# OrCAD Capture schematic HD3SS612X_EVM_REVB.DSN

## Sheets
1 PAGE1_Block Power Diagram: size A4; title: HD3SS612x 2 to 1 switch; rev: 1.0; company: Texas Instrument
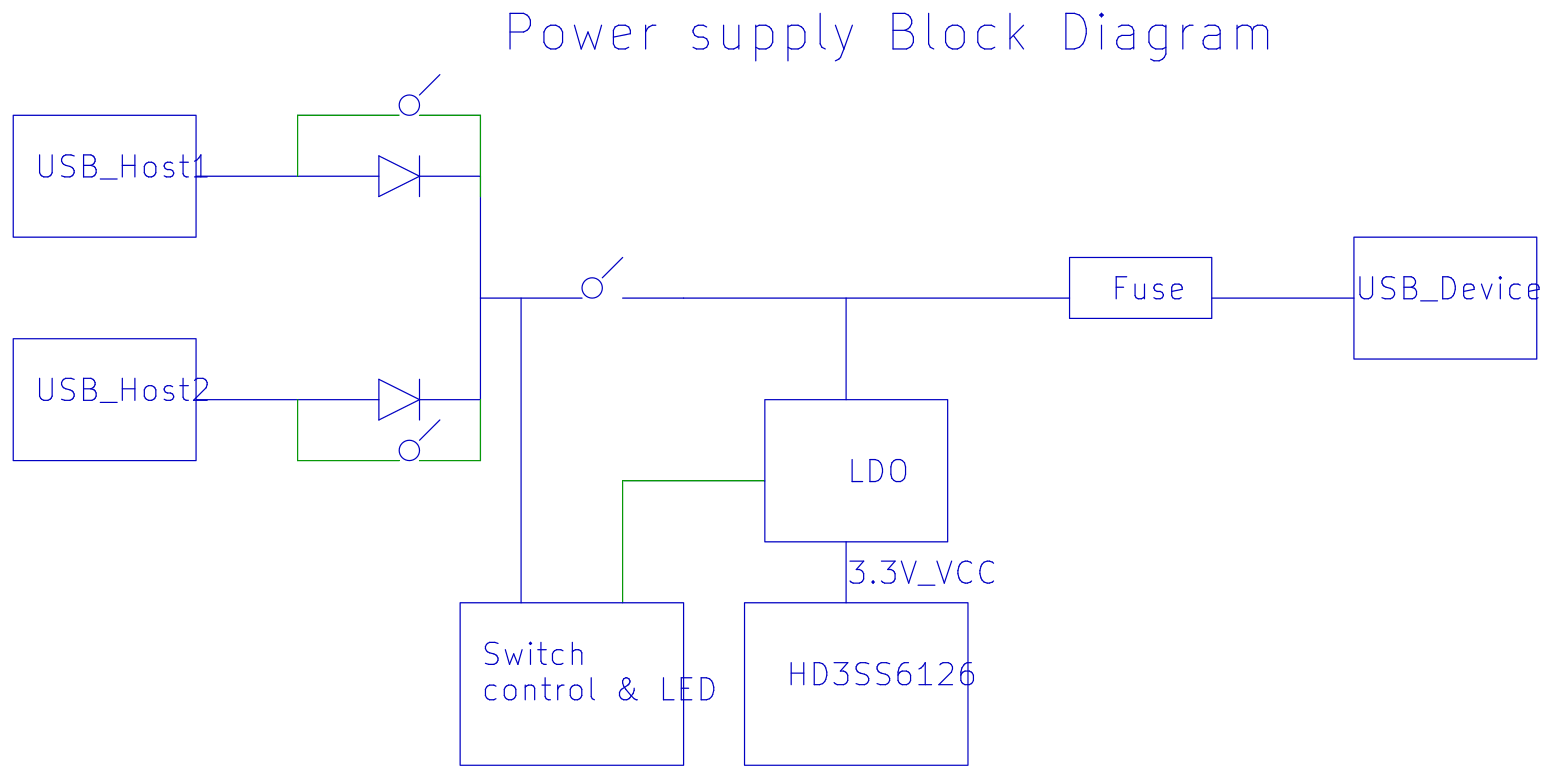
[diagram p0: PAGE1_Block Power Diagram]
2 PAGE4_USB_Micro-B Connectors: size A4
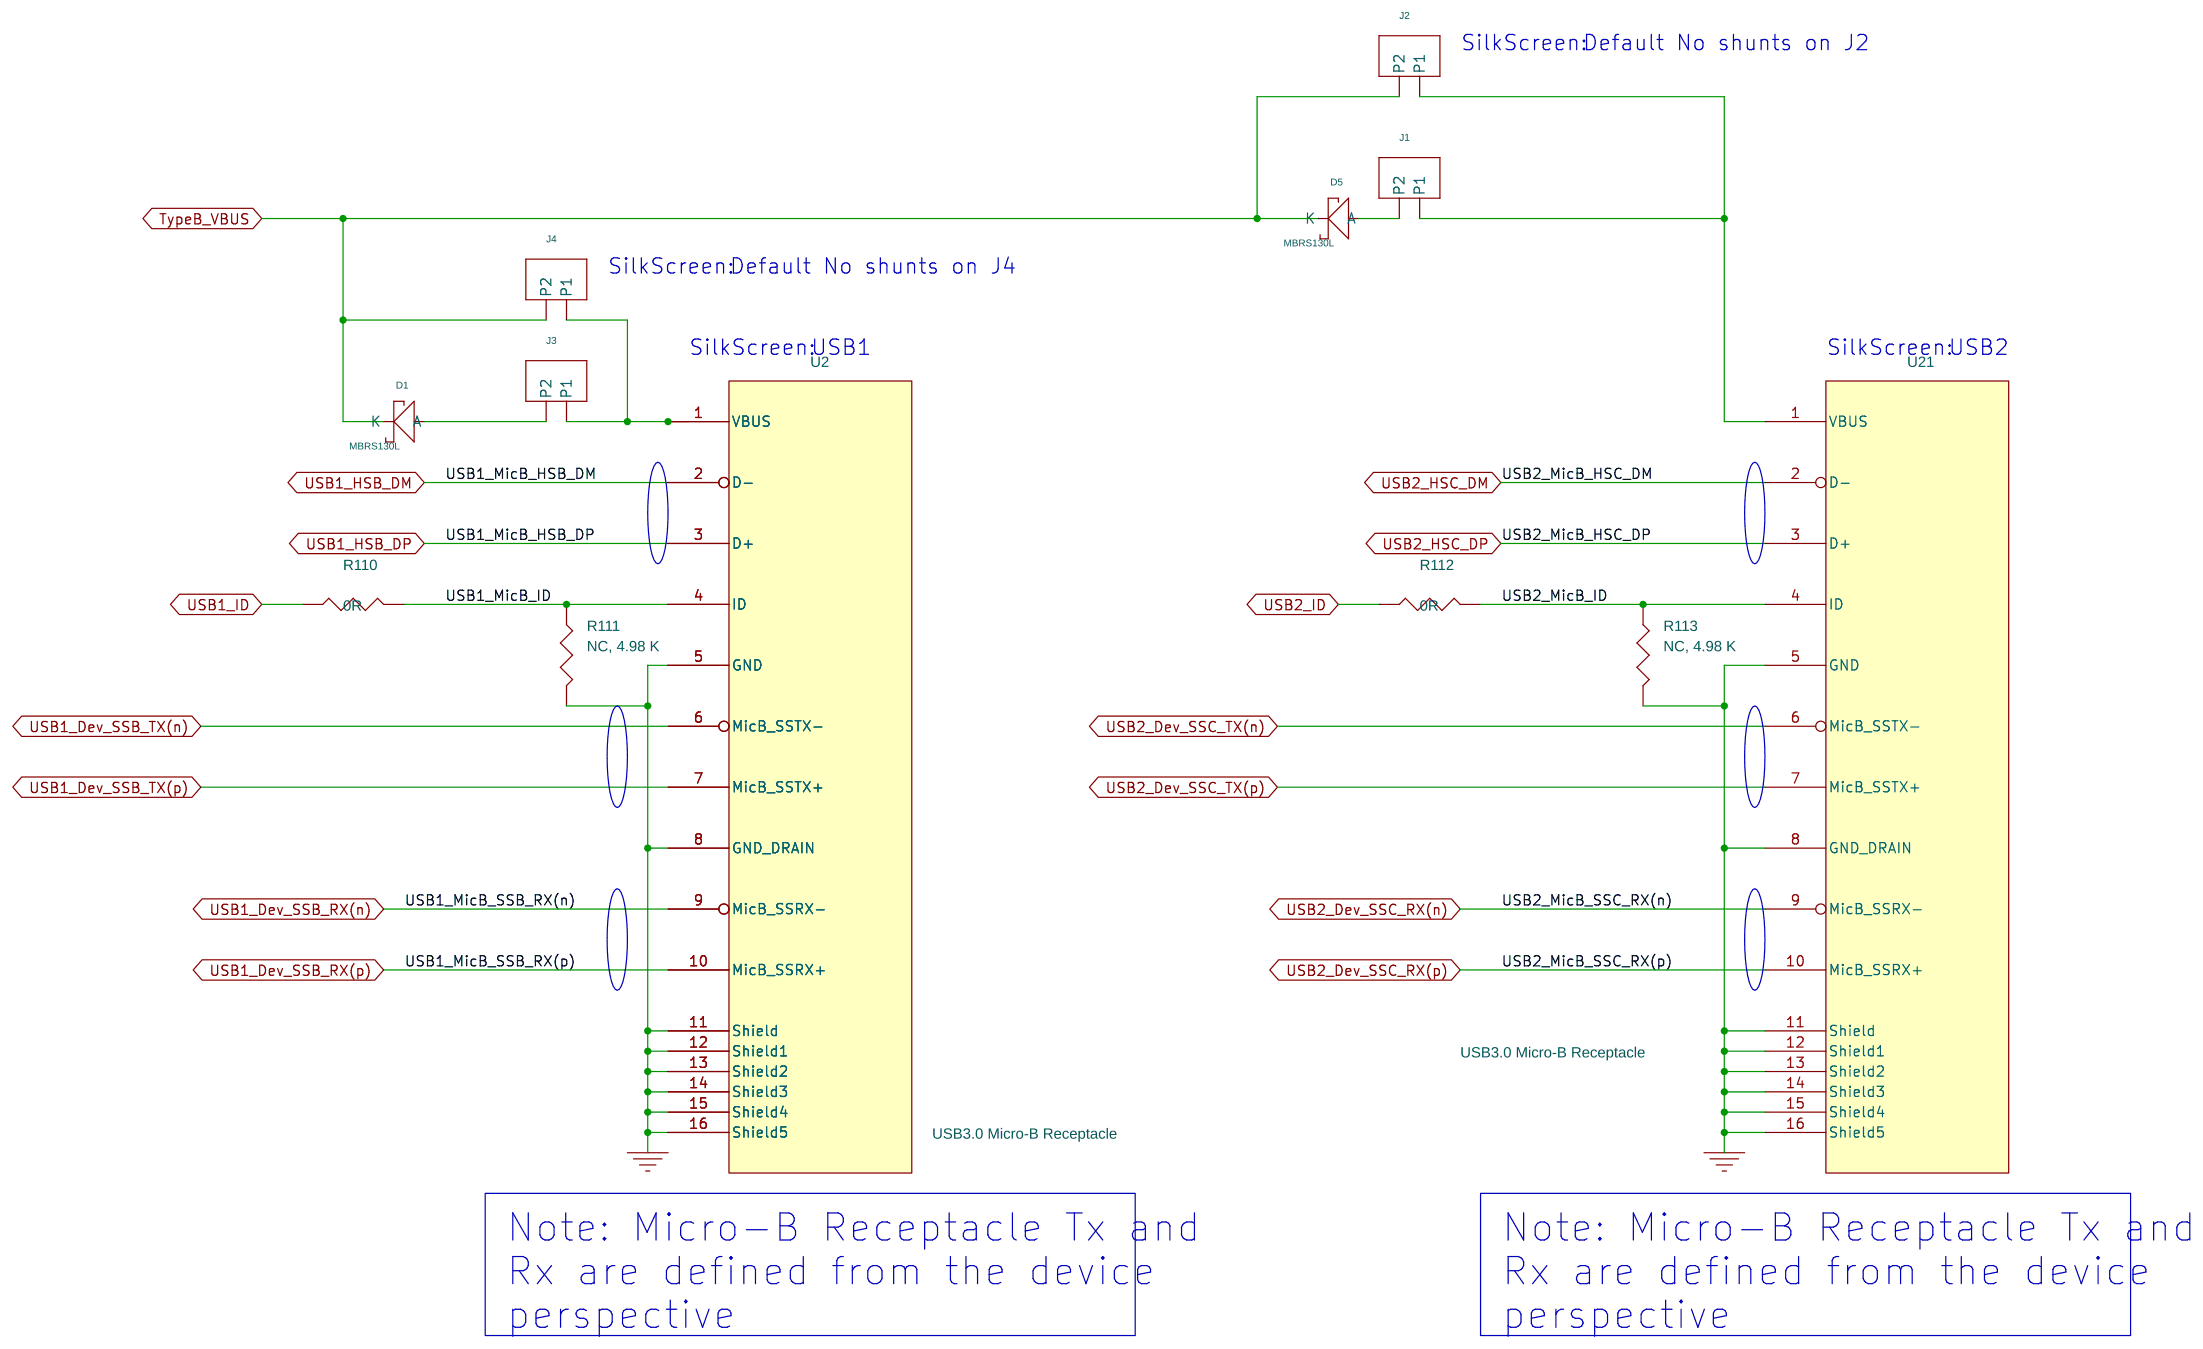
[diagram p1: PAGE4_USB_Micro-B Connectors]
3 PAGE3_Power and Switch control: size A4
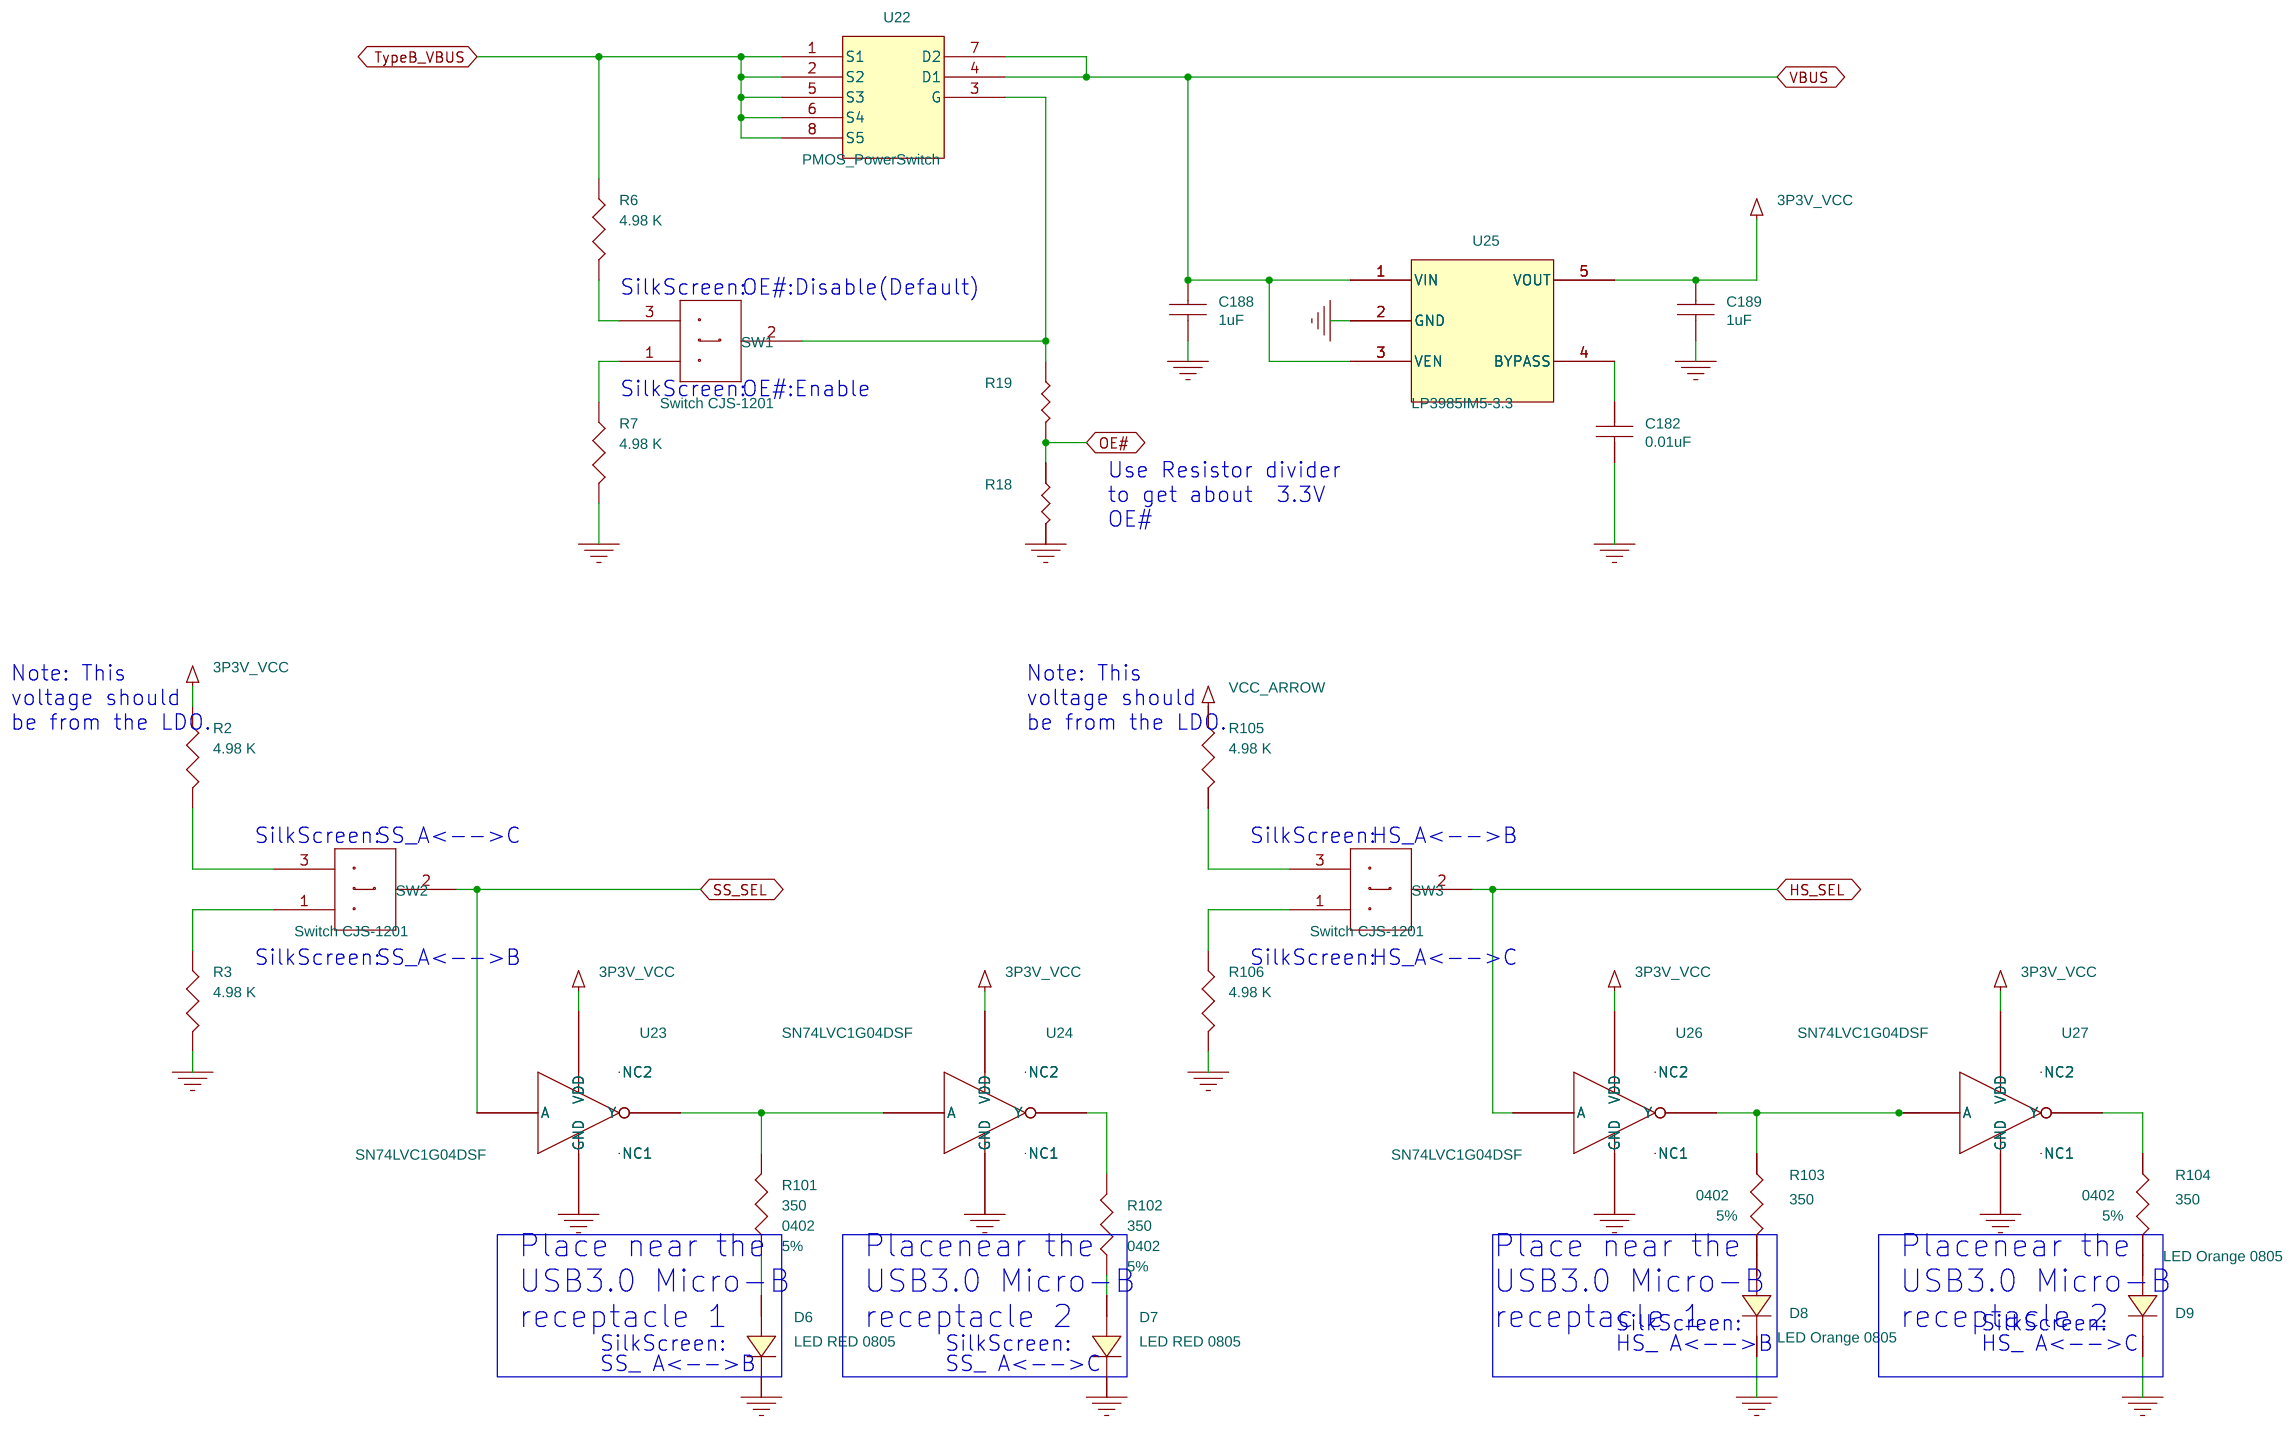
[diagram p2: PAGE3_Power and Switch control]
4 PAGE2_HD3SS6128: size A4
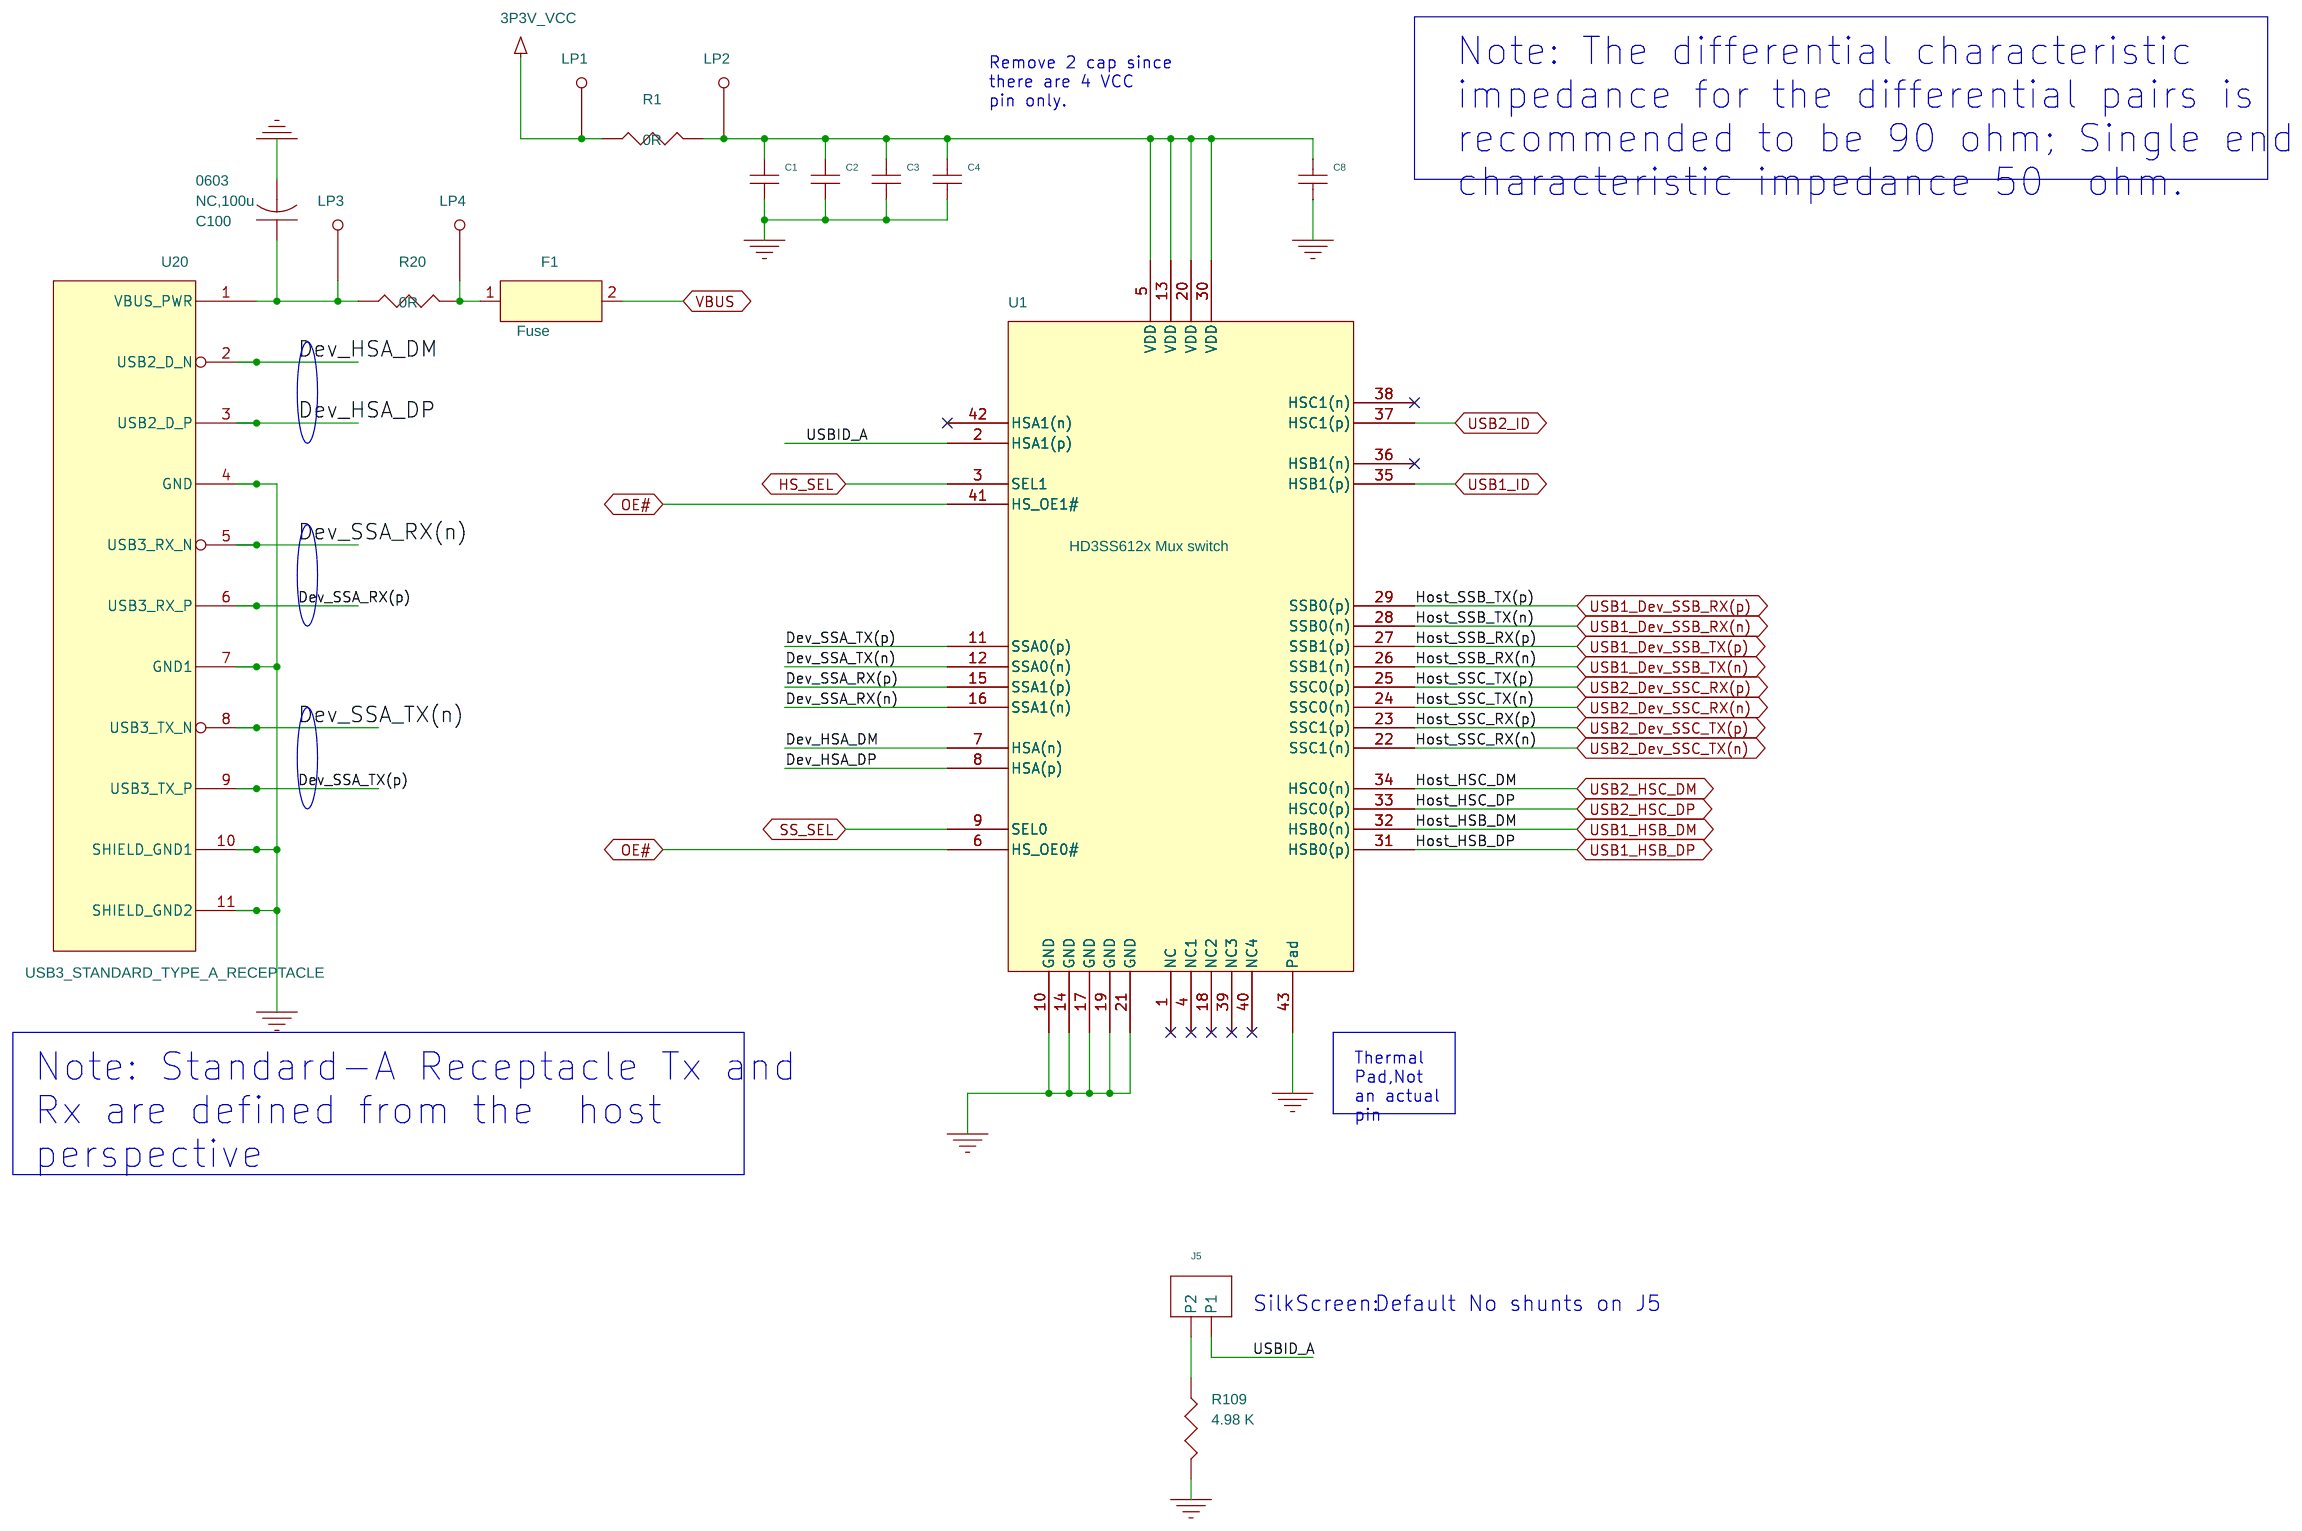
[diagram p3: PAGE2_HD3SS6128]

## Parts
sheet PAGE2_HD3SS6128
C1  0.1uF  [0402]
C2  0.1uF  [0402]
C3  0.1uF  [0402]
C4  0.1uF  [0402]
C8  NC, 10uF  [0805]
C100  NC,100u  [0603]
F1  Fuse  [1206]
J5  CON02  [BERG1X2]
LP1  LP  [TESTLOOP]
LP2  LP  [TESTLOOP]
LP3  LP  [TESTLOOP]
LP4  LP  [TESTLOOP]
R1  0R  [0402]
R20  0R  [0402]
R109  4.98 K  [0603]
U1  HD3SS612x Mux switch  [IRONWOOD_42pin_c9856]
U20  USB3_STANDARD_TYPE_A_RECEPTACLE  [usb3_typea]
sheet PAGE3_Power and Switch control
C182  0.01uF  [0402]
C188  1uF  [0603]
C189  1uF  [0603]
D6  LED RED 0805  [0805]
D7  LED RED 0805  [0805]
D8  LED Orange 0805  [0805]
D9  LED Orange 0805  [0805]
R2  4.98 K  [0603]
R3  4.98 K  [0603]
R6  4.98 K  [0603]
R7  4.98 K  [0603]
R18  100K  [0402]
R19  50K  [0402]
R101  350  [0402]
R102  350  [0402]
R103  350  [0402]
R104  350  [0402]
R105  4.98 K  [0603]
R106  4.98 K  [0603]
SW1  Switch CJS-1201  [CJS-1200B]
SW2  Switch CJS-1201  [CJS-1200B]
SW3  Switch CJS-1201  [CJS-1200B]
U22  PMOS_PowerSwitch  [csd25302q2]
U23  SN74LVC1G04DSF  [DSF]
U24  SN74LVC1G04DSF  [DSF]
U25  LP3985IM5-3.3  [dbv_r-pdso-g5]
U26  SN74LVC1G04DSF  [DSF]
U27  SN74LVC1G04DSF  [DSF]
sheet PAGE4_USB_Micro-B Connectors
D1  SCHOTTKY  [DO-214AA]
D5  SCHOTTKY  [DO-214AA]
J1  CON02  [BERG1X2]
J2  CON02  [BERG1X2]
J3  CON02  [BERG1X2]
J4  CON02  [BERG1X2]
R110  0R  [0402]
R111  NC, 4.98 K  [0603]
R112  0R  [0402]
R113  NC, 4.98 K  [0603]
U2  USB3.0 Micro-B Receptacle  [USB3_micro_b_receptacle]
U21  USB3.0 Micro-B Receptacle  [USB3_micro_b_receptacle]

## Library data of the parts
C1-C4 = CAP: 10V; $SEC: 1; ATIPartNo: 4170010400G; CDS_LIB: capacitor; DRAWING: @LIGHTNING_BOLT_NB_LIB.NOTE_BOOK(SCH_1):PAGE1; PHYS_PAGE: 1; ROT: 0; TOLERANCE: 10%; VER: 1; VOLTAGE: 10V; XY: (-8600,5400)
C8 = CAP: 6.3V; $SEC: 1; ATIPartNo: 4210010600G; CDS_LIB: capacitor; DRAWING: @LIGHTNING_BOLT_NB_LIB.NOTE_BOOK(SCH_1):PAGE1; PHYS_PAGE: 1; ROT: 0; TOLERANCE: 10%; VER: 1; VOLTAGE: 6.3V; XY: (-9500,3550)
C100 = PCap_CaseD: TYPE: Tantalum
F1 = Fuse_0
J1-J5 = CON02: ATIPartNo: 6010014900G; CDS_LIB: connector; DRAWING: @LIGHTNING_BOLT_NB_LIB.NOTE_BOOK(SCH_1):PAGE2; PHYS_PAGE: 2; ROT: 0; VER: 1; XY: (-8200,6300)
LP1-LP4 = TESTLOOP: Manuf: KOBIKONN; Manuf PN: 151-103-RC
R1 R20 R110 R112 = R: Resistor; Tolerance: 5%
R2 R3 R6 R7 R105 R106 R109 R111 R113 = r0603: Manufacturer: Any; Manufacturer Part Number: Any
U1 = HD3SS6126_Mux_switch_11
U20 = TMP_0
C182 C188 C189 = CAP_NP: 6.3V Capacitor
D6 D7 = DIODE: Manuf: Rohm; Manuf PN: SML-211UT
D8 D9 = DIODE: Manuf: Rohm; Manuf PN: SML-211DTT86
R18 R19 = RES: $SEC: 1; ATIPartNo: 3150010400G; CDS_LIB: resistor; DRAWING: @LIGHTNING_BOLT_NB_LIB.NOTE_BOOK(SCH_1):PAGE1; PHYS_PAGE: 1; ROT: 4; TOLERANCE: 5%; VER: 1; WATTAGE: 1/16W; XY: (-9550,4950)
R101-R104 = R_4: Tolerance: 5%
SW1-SW3 = Switch_CJS-1201
U22 = PMOS_PowerSwitch_3
U23 U24 U26 U27 = SN74LVC1G04DSF
U25 = LP3985IM5-3_0.3
D1 D5 = SCHOTTKY: Diode; $SEC: 1; ATIPartNo: 5170000800G; CDS_LIB: diode; CURRENT: 2A; DEVICE_NAME: MBRS130L; DRAWING: @LIGHTNING_BOLT_NB_LIB.NOTE_BOOK(SCH_1):PAGE1; Digi-Key Part Number: RB751V-40-TPMSCT-ND; Manufacturer: Fairchild; Manufacturer Part Number: MBRS130L; Manufacturer's Part Number: MBRS130L; PHYS_PAGE: 1; ROT: 0; TOLERANCE: NA; VER: 1; VOLTAGE: 40V; XY: (-1750,3700)
U2 = USB3_1.0_Micro-B_Receptacle: Manufacturer: Amphenol Commercial Products; Manufacturer Part Number: GSB343133HR
U21 = USB3_2.0_Micro-B_Receptacle: Manufacturer: Amphenol Commercial Products; Manufacturer Part Number: GSB343133HR

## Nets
GND: C1.2(B) C2.2(B) C3.2(B) C4.2(B) C8.2(B) C100.2 C182.2 C188.2 C189.2 D6.2(K) D7.2(K) D8.2(K) D9.2(K) R3.2 R7.2 R18.2(B) R106.2 R109.2 R111.2 R113.2 U1.10(GND) U1.14(GND) U1.17(GND) U1.19(GND) U1.21(GND) U1.43(Pad) U2.5(GND) U2.8(GND_DRAIN) U2.11(Shield) U2.12(Shield1) U2.13(Shield2) U2.14(Shield3) U2.15(Shield4) U2.16(Shield5) U20.4(GND) U20.7(GND1) U20.10(SHIELD_GND1) U20.11(SHIELD_GND2) U21.5(GND) U21.8(GND_DRAIN) U21.11(Shield) U21.12(Shield1) U21.13(Shield2) U21.14(Shield3) U21.15(Shield4) U21.16(Shield5) U23.3(GND) U24.3(GND) U25.2(GND) U26.3(GND) U27.3(GND)
VBUS: C188.1 F1.2 U22.4(D1) U22.7(D2) U25.1(VIN) U25.3(VEN)
3P3V_VCC: C189.1 LP1.1 R1.1 R2.1 R105.1 U23.6(VDD) U24.6(VDD) U25.5(VOUT) U26.6(VDD) U27.6(VDD)
Dev_HSA_DM: U1.7(HSA(n)) U20.2(USB2_D_N)
Dev_HSA_DP: U1.8(HSA(p)) U20.3(USB2_D_P)
Dev_SSA_RX(n): U1.16(SSA1(n)) U20.5(USB3_RX_N)
Dev_SSA_RX(p): U1.15(SSA1(p)) U20.6(USB3_RX_P)
Dev_SSA_TX(n): U1.12(SSA0(n)) U20.8(USB3_TX_N)
Dev_SSA_TX(p): U1.11(SSA0(p)) U20.9(USB3_TX_P)
HS_SEL: SW3.2 U1.3(SEL1) U26.2(A)
OE#: R18.1(A) R19.2(B) U1.6(HS_OE0#) U1.41(HS_OE1#)
SS_SEL: SW2.2 U1.9(SEL0) U23.2(A)
TypeB_VBUS: D1.1(K) D5.1(K) J2.2(P2) J4.2(P2) R6.1 U22.1(S1) U22.2(S2) U22.5(S3) U22.6(S4) U22.8(S5)
USB1_Dev_SSB_RX(n): U1.28(SSB0(n)) U2.9(MicB_SSRX-)
USB1_Dev_SSB_RX(p): U1.29(SSB0(p)) U2.10(MicB_SSRX+)
USB1_Dev_SSB_TX(n): U1.26(SSB1(n)) U2.6(MicB_SSTX-)
USB1_Dev_SSB_TX(p): U1.27(SSB1(p)) U2.7(MicB_SSTX+)
USB1_HSB_DM: U1.32(HSB0(n)) U2.2(D-)
USB1_HSB_DP: U1.31(HSB0(p)) U2.3(D+)
USB1_ID: R110.1 U1.35(HSB1(p))
USB1_MicB_ID: R110.2 R111.1 U2.4(ID)
USB2_Dev_SSC_RX(n): U1.24(SSC0(n)) U21.9(MicB_SSRX-)
USB2_Dev_SSC_RX(p): U1.25(SSC0(p)) U21.10(MicB_SSRX+)
USB2_Dev_SSC_TX(n): U1.22(SSC1(n)) U21.6(MicB_SSTX-)
USB2_Dev_SSC_TX(p): U1.23(SSC1(p)) U21.7(MicB_SSTX+)
USB2_HSC_DM: U1.34(HSC0(n)) U21.2(D-)
USB2_HSC_DP: U1.33(HSC0(p)) U21.3(D+)
USB2_ID: R112.1 U1.37(HSC1(p))
USB2_MicB_ID: R112.2 R113.1 U21.4(ID)
USBID_A: J5.1(P1) U1.2(HSA1(p))
N16697677: C1.1(A) C2.1(A) C3.1(A) C4.1(A) C8.1(A) LP2.1 R1.2 U1.5(VDD) U1.13(VDD) U1.20(VDD) U1.30(VDD)
N16756461: J1.1(P1) J2.1(P1) U21.1(VBUS)
N16757635: R19.1(A) SW1.2 U22.3(G)
N16757641: R7.1 SW1.1
N16757645: R6.2 SW1.3
N16758482: R2.2 SW2.3
N16758486: R3.1 SW2.1
N16761498: D7.1(A) R102.1
N16761564: D6.1(A) R101.1
N16761768: R101.2 U23.4(Y) U24.2(A)
N16762868: R102.2 U24.4(Y)
N16774048: C182.1 U25.4(BYPASS)
N16774634: C100.1 LP3.1 R20.1 U20.1(VBUS_PWR)
N16774662: F1.1 LP4.1 R20.2
N16778774: D5.2(A) J1.2(P2)
N16778838: J3.1(P1) J4.1(P1) U2.1(VBUS)
N16778841: D1.2(A) J3.2(P2)
N16779573: R105.2 SW3.3
N16779575: R106.1 SW3.1
N16780231: R103.1 U26.4(Y) U27.2(A)
N16780380: R104.1 U27.4(Y)
N16785274: J5.2(P2) R109.1
N16809079: D8.1(A) R103.2
N16809080: D9.1(A) R104.2

Not connected (* = marked no-connect by the designer): U1 1(NC)* 4(NC1)* 18(NC2)* 36(HSB1(n))* 38(HSC1(n))* 39(NC3)* 40(NC4)* 42(HSA1(n))*; U23 1(NC1) 5(NC2); U24 1(NC1) 5(NC2); U26 1(NC1) 5(NC2); U27 1(NC1) 5(NC2)

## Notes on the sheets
sheet 1
- Power supply Block Diagram
- USB_Host1
- Fuse
- USB_Device
- USB_Host2
- LDO
- 3.3V_VCC
- Switch
  control & LED
- HD3SS6126
sheet 2
- SilkScreen:
- Default No shunts on J2
- SilkScreen:
- Default No shunts on J4
- SilkScreen:
- USB1
- SilkScreen:
- USB2
- Note: Micro-B Receptacle Tx and
  Rx are defined from the device
  perspective
- Note: Micro-B Receptacle Tx and
  Rx are defined from the device
  perspective
sheet 3
- SilkScreen:
- OE#:Disable(Default)
- SilkScreen:
- OE#:Enable
- Use Resistor divider
  to get about  3.3V
  OE#
- Note: This
  voltage should
  be from the LDO.
- Note: This
  voltage should
  be from the LDO.
- SilkScreen:
- SS_A<-->C
- SilkScreen:
- HS_A<-->B
- SilkScreen:
- SS_A<-->B
- SilkScreen:
- HS_A<-->C
- Place near the
  USB3.0 Micro-B
  receptacle 1
- Placenear the
  USB3.0 Micro-B
  receptacle 2
- Place near the
  USB3.0 Micro-B
  receptacle 1
- Placenear the
  USB3.0 Micro-B
  receptacle 2
- SilkScreen:
- SilkScreen:
- SilkScreen:
- SilkScreen:
- HS_ A<-->B
- HS_ A<-->C
- SS_ A<-->B
- SS_ A<-->C
sheet 4
- Note: The differential characteristic
  impedance for the differential pairs is
  recommended to be 90 ohm; Single end
  characteristic impedance 50  ohm.
- Remove 2 cap since
  there are 4 VCC
  pin only.
- Note: Standard-A Receptacle Tx and
  Rx are defined from the  host
  perspective
- Thermal
  Pad,Not
  an actual
  pin
- SilkScreen:
- Default No shunts on J5
